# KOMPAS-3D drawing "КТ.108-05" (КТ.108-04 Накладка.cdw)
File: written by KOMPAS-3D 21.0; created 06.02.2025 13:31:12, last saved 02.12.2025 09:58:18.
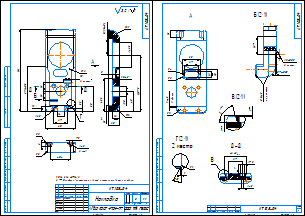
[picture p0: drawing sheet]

Sheets 1-2: A3, portrait

Document properties: Автор: User; Организация: User; Полное имя файла: C:\Users\User\Desktop\Pelorus PRO доработки\накладка\КТ.108-04 Накладка.cdw; Знак неуказанной шероховатости: 4; Параметр неуказанной шероховатости: 3,2; Форматы листов документа: 2xA3

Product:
- Part/product: КТ.108-05
    Комментарий: User

Title block, sheet 1: Наименование: Накладка; designation: КТ.108-04; Материал: АМг6 ГОСТ 4784-97; Масса: 0; sheet number: 1; Количество листов документа: 2; organisation: ООО ТПК Пегас; Форматы листов документа: A3; stored path: D:\Marat\work\eholot\KazanTarget\Новые проекты\КТ Pro\детали\Накладка Г 68\Накладка Г 68.cdw; Разработал: Гайсин
Title block, sheet 2: sheet number: 2

Views: Вид 1, Местный разрез 1, Спереди, Проекционный вид 2, Проекционный вид 3, Вид по стрелке А, Разрез Д-Д, Выносной элемент 9, Вид по стрелке Б, Выносной элемент 11, Выносной элемент В, Выносной элемент, Выносной элемент Г
Referenced files in D:\Marat\work\eholot\KazanTarget\Новые проекты\КТ Pro\детали\Накладка Г 68\: Накладка Г 68.m3d
Referenced files in C:\Users\User\Desktop\Pelorus PRO доработки\накладка\: КТ.108-05.m3d, КТ.108-04.m3d
Referenced files in D:\Marat\work\eholot\KazanTarget\Новые проекты\КТ Pro\детали\Накладка с отверстием\: Накладка с отверстием.m3d
Referenced files in D:\Marat\work\eholot\KazanTarget\детали\детали KT Pro 1\КТ.108-01 Накладка\: КТ.108-01 Накладка.m3d
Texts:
  КТ.108-05
  по контуру
Dimensions and other numbers on the sheet: 12; 20; 48,5; 5; 110,75; 65,5; 21; 1,5; 32,25±0,1; 40; 13; 161; 60; 14; 11; 27; 6,5; 5,5; 50; 89,2±0,5; 15; 2 места; 18; 40,4; 8; 7,5; 4,5; 2 отв; 35; 4; 2; 2 фаски; 7; 42,45; 1; 0,7±0,05; 0,5х45; 3,2; 1:1; 0

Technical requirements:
  H14, h14, ±IT14/2.
  ** Профиль "ласточкин хвост" контролировать калибром.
